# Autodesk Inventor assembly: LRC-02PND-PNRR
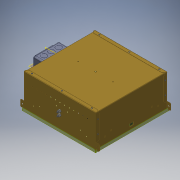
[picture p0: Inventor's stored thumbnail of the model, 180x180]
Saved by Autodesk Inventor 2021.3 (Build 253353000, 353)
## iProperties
Part Number: LRC-02PND-PNRR
Document SubType Name: Assembly
Designer: JChurch
Author: JChurch
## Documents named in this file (4)
- X:\Revit Files\0000-Un-Zipped\COB\LRC-02PND-PNR\LRC-02PND-PNRR.iam
- X:\INVENTOR\830\830520-00-00.ipt
- X:\INVENTOR\881\881088-00-00.iam
- X:\INVENTOR\750\750453-02-XX.iam
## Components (3 placed, 3 different names)
1. 830520-00-00:1 — Mate:1, Mate:2, Mate:3, Mate:4, Tangent:1, Angle:1, Insert:1
2. 881088-00-00:1 [sub-assembly] — Mate:4, Tangent:1, Angle:1
3. 750453-02-XX:1 [sub-assembly] — Insert:1
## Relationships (7: Mate 4, Tangent 1, Angle 1, Insert 1)
- Mate:1: 830520-00-00:1
- Mate:2: 830520-00-00:1
- Mate:3: 830520-00-00:1
- Mate:4: 830520-00-00:1 ↔ 881088-00-00:1
- Tangent:1: 830520-00-00:1 ↔ 881088-00-00:1
- Angle:1: 830520-00-00:1 ↔ 881088-00-00:1
- Insert:1: 830520-00-00:1 ↔ 750453-02-XX:1
